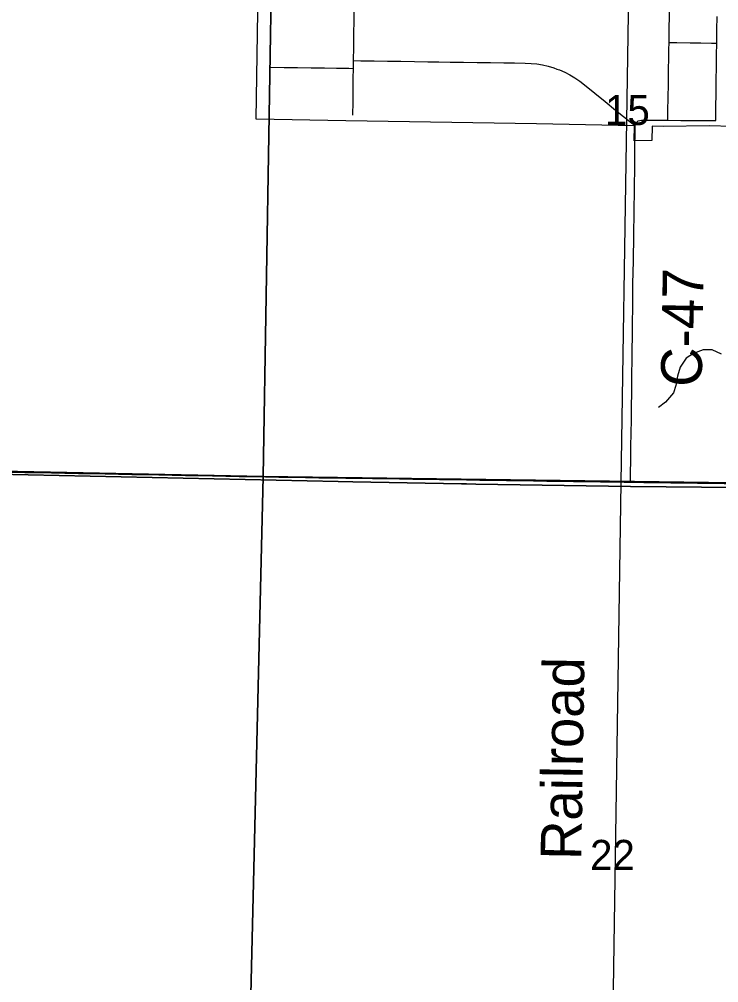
# Model space of a CAD drawing. Extents: x 0 to 34, y 0 to 22.
# Drawn here: x 4.43 to 5.403, y 15.728 to 17.068 of the extents above; entities that cross this region are included whole.
import ezdxf

# ---------------------------------------------------------------- set-up
doc = ezdxf.new("R2010")
doc.units = 0
for name, color, linetype in [('GM_X_City_Street', 7, 'Continuous'), ('GM_X_Corporation', 7, 'Continuous'), ('GM_X_County_Road', 7, 'Continuous'), ('GM_X_County_Road_Text', 7, 'Continuous'), ('GM_X_Minor_River', 7, 'Continuous'), ('GM_X_Rail_Line', 7, 'Continuous'), ('GM_X_Rail_Line_Text', 7, 'Continuous'), ('GM_X_Section_Text', 7, 'Continuous')]:
    doc.layers.add(name, color=color, linetype=linetype)

msp = doc.modelspace()

# ---------------------------------------------------------------- linework, layer by layer
at = {"layer": 'GM_X_City_Street'}
msp.add_line((4.8949, 16.9997), (4.8951, 17.0104), dxfattribs=at)
for points in [[(5.332, 16.9275), (5.3322, 16.9405), (5.3325, 16.9592), (5.3328, 16.9778), (5.3331, 16.9965), (5.3334, 17.0151), (5.3336, 17.0254), (5.3338, 17.0358), (5.3341, 17.0544), (5.3343, 17.0731), (5.3346, 17.0917), (5.3348, 17.1051), (5.335, 17.1184), (5.3352, 17.1371), (5.3355, 17.1557), (5.3357, 17.1744), (5.336, 17.193), (5.3361, 17.2027), (5.3363, 17.2123)], [(4.8951, 17.0104), (4.8953, 17.029), (4.8956, 17.0477), (4.8958, 17.0663), (4.8961, 17.085)], [(5.3338, 17.0358), (5.3445, 17.0356), (5.3631, 17.0352), (5.378, 17.035), (5.3928, 17.0347), (5.4001, 17.0346)], [(4.8951, 17.0104), (4.905, 17.0103), (4.9237, 17.01), (4.9423, 17.0097), (4.9609, 17.0095), (4.9796, 17.0092), (4.9982, 17.0089), (5.0138, 17.0087), (5.0295, 17.0085), (5.0481, 17.0082), (5.0668, 17.008), (5.0854, 17.0077), (5.104, 17.0074), (5.1189, 17.0072), (5.1337, 17.007), (5.1418, 17.0066), (5.1499, 17.0058), (5.1579, 17.0044), (5.1658, 17.0026), (5.1736, 17.0003), (5.1775, 16.9988), (5.1812, 16.9975), (5.1886, 16.9942), (5.1958, 16.9905), (5.2028, 16.9864), (5.2095, 16.9818), (5.216, 16.9769), (5.2305, 16.9652), (5.245, 16.9535), (5.2595, 16.9417), (5.2706, 16.9328), (5.2817, 16.9238), (5.2866, 16.9201)], [(4.78, 17.0014), (4.7986, 17.0011), (4.8172, 17.0009), (4.8359, 17.0006), (4.8545, 17.0003), (4.8715, 17.0001), (4.8884, 16.9998), (4.8949, 16.9997)], [(4.8941, 16.9345), (4.8943, 16.9531), (4.8946, 16.9717), (4.8947, 16.9857), (4.8949, 16.9997)]]:
    msp.add_lwpolyline(points, dxfattribs=at)
at = {"layer": 'GM_X_Corporation'}
for points in [[(4.7862, 17.4375), (4.7695, 16.4317), (3.7672, 16.4521), (3.785, 17.4549)], [(4.7862, 17.4375), (5.7831, 17.4286), (5.7675, 16.4186), (4.7695, 16.4317)], [(4.7695, 16.4317), (4.7451, 15.4188), (3.745, 15.438), (3.7672, 16.4521)], [(5.7675, 16.4186), (5.7454, 15.4068), (4.7451, 15.4188), (4.7695, 16.4317)]]:
    msp.add_lwpolyline(points, close=True, dxfattribs=at)
for points in [[(5.4212, 16.9189), (5.3901, 16.9199), (5.3255, 16.9188), (5.3101, 16.9191), (5.3098, 16.8992), (5.2851, 16.8987), (5.2857, 16.9196), (5.1495, 16.9223), (4.8842, 16.9269), (4.7597, 16.9291), (4.7677, 17.4357)], [(4.2697, 16.4379), (4.8738, 16.4249), (4.894, 16.4245), (5.045, 16.4217), (5.0523, 16.4215), (5.0651, 16.4213), (5.28, 16.4182), (5.4285, 16.4168), (5.6885, 16.4169), (6.7715, 16.4096), (7.7624, 16.3866)], [(7.7624, 16.3866), (6.7715, 16.4096), (5.6885, 16.4169), (5.4285, 16.4168), (5.28, 16.4182), (5.0651, 16.4213), (5.0523, 16.4215), (5.045, 16.4217), (4.894, 16.4245), (4.8738, 16.4249), (4.2697, 16.4379)]]:
    msp.add_lwpolyline(points, dxfattribs=at)
at = {"layer": 'GM_X_County_Road'}
for points in [[(5.3986, 16.9273), (5.3989, 16.9459), (5.3991, 16.9646), (5.3994, 16.9832), (5.3996, 17.0019), (5.3999, 17.0182), (5.4001, 17.0346), (5.4004, 17.0532), (5.4006, 17.0718)], [(5.2865, 16.9079), (5.2866, 16.9201), (5.2872, 16.9229), (5.2879, 16.9244), (5.2892, 16.9255), (5.2908, 16.9267)], [(5.2908, 16.9267), (5.293, 16.9272), (5.2953, 16.9275), (5.2991, 16.9275), (5.3173, 16.9275), (5.332, 16.9275), (5.35, 16.9273), (5.369, 16.9271), (5.3852, 16.927), (5.3986, 16.9273)], [(5.28, 16.424), (5.2802, 16.4363), (5.2805, 16.455), (5.2808, 16.4736), (5.2811, 16.4923), (5.2814, 16.5109), (5.2817, 16.5295), (5.2819, 16.5482), (5.282, 16.5682), (5.2825, 16.5998), (5.2829, 16.6355), (5.2834, 16.677), (5.2836, 16.6999), (5.2843, 16.7317), (5.2847, 16.7676), (5.2852, 16.8003), (5.2857, 16.8314), (5.2861, 16.8648), (5.2864, 16.8934), (5.2865, 16.9079)], [(4.4192, 16.4381), (4.4378, 16.4377), (4.4564, 16.4373), (4.4751, 16.437), (4.4937, 16.4366), (4.5124, 16.4363), (4.531, 16.4359), (4.5496, 16.4356), (4.5683, 16.4352), (4.5869, 16.4349), (4.6055, 16.4345), (4.6242, 16.4341), (4.6428, 16.4338), (4.6614, 16.4334), (4.6801, 16.4331), (4.6987, 16.4327), (4.7173, 16.4324), (4.736, 16.432), (4.7542, 16.4317), (4.7724, 16.4313), (4.791, 16.431), (4.8097, 16.4308), (4.8283, 16.4305), (4.8469, 16.4302), (4.8656, 16.43), (4.8842, 16.4297), (4.9029, 16.4294), (4.9215, 16.4291), (4.9401, 16.4289), (4.9588, 16.4286), (4.9774, 16.4283), (4.9961, 16.4281), (5.0147, 16.4278), (5.0333, 16.4275), (5.052, 16.4273), (5.0706, 16.427), (5.0893, 16.4267), (5.1079, 16.4264), (5.1266, 16.4262), (5.1452, 16.4259), (5.1638, 16.4256), (5.1825, 16.4254), (5.2011, 16.4251), (5.2198, 16.4248), (5.2384, 16.4246), (5.2549, 16.4243), (5.2713, 16.4241), (5.28, 16.424)], [(5.28, 16.424), (5.2987, 16.4237), (5.3173, 16.4235), (5.336, 16.4232), (5.3546, 16.423), (5.3732, 16.4228), (5.3919, 16.4225), (5.4105, 16.4223), (5.4292, 16.422), (5.4478, 16.4218), (5.4664, 16.4216), (5.4851, 16.4213), (5.5037, 16.4211), (5.5224, 16.4209), (5.541, 16.4206), (5.5597, 16.4204), (5.5692, 16.4203), (5.5788, 16.4201)]]:
    msp.add_lwpolyline(points, dxfattribs=at)
at = {"layer": 'GM_X_Minor_River'}
msp.add_lwpolyline([(5.4067, 16.602), (5.3939, 16.608), (5.3814, 16.6083), (5.3676, 16.6029), (5.3576, 16.5963), (5.3494, 16.5839), (5.3457, 16.5715), (5.3431, 16.5586), (5.3399, 16.5484), (5.329, 16.5354), (5.3189, 16.528)], dxfattribs=at)
at = {"layer": 'GM_X_Rail_Line'}
msp.add_lwpolyline([(5.2312, 14.404), (5.2346, 14.4124), (5.2368, 14.4226), (5.243, 14.9028), (5.2517, 15.4121), (5.2672, 16.4237), (5.283, 17.4313), (5.2899, 17.8728), (5.3076, 19.0241), (5.3057, 19.0962), (5.3011, 19.1491), (5.2883, 19.2066), (5.0953, 19.84), (5.0724, 19.9157), (5.0587, 19.9632), (5.0513, 20.0198), (5.0584, 20.4524), (5.0684, 20.9)], dxfattribs=at)

# ---------------------------------------------------------------- texts
at = {"layer": 'GM_X_County_Road_Text'}
msp.add_text('C-47', height=0.05682, rotation=89.023, dxfattribs=at).set_placement((5.3791, 16.5563))
at = {"layer": 'GM_X_Rail_Line_Text'}
msp.add_text('Railroad', height=0.05663, rotation=89.1027, dxfattribs=at).set_placement((5.2117, 15.8982))
at = {"layer": 'GM_X_Section_Text'}
for s, p in [('15', (5.2447, 16.9209)), ('22', (5.2239, 15.8845))]:
    msp.add_text(s, height=0.04186, rotation=0, dxfattribs=at).set_placement(p)

doc.saveas('drawing.dxf')
